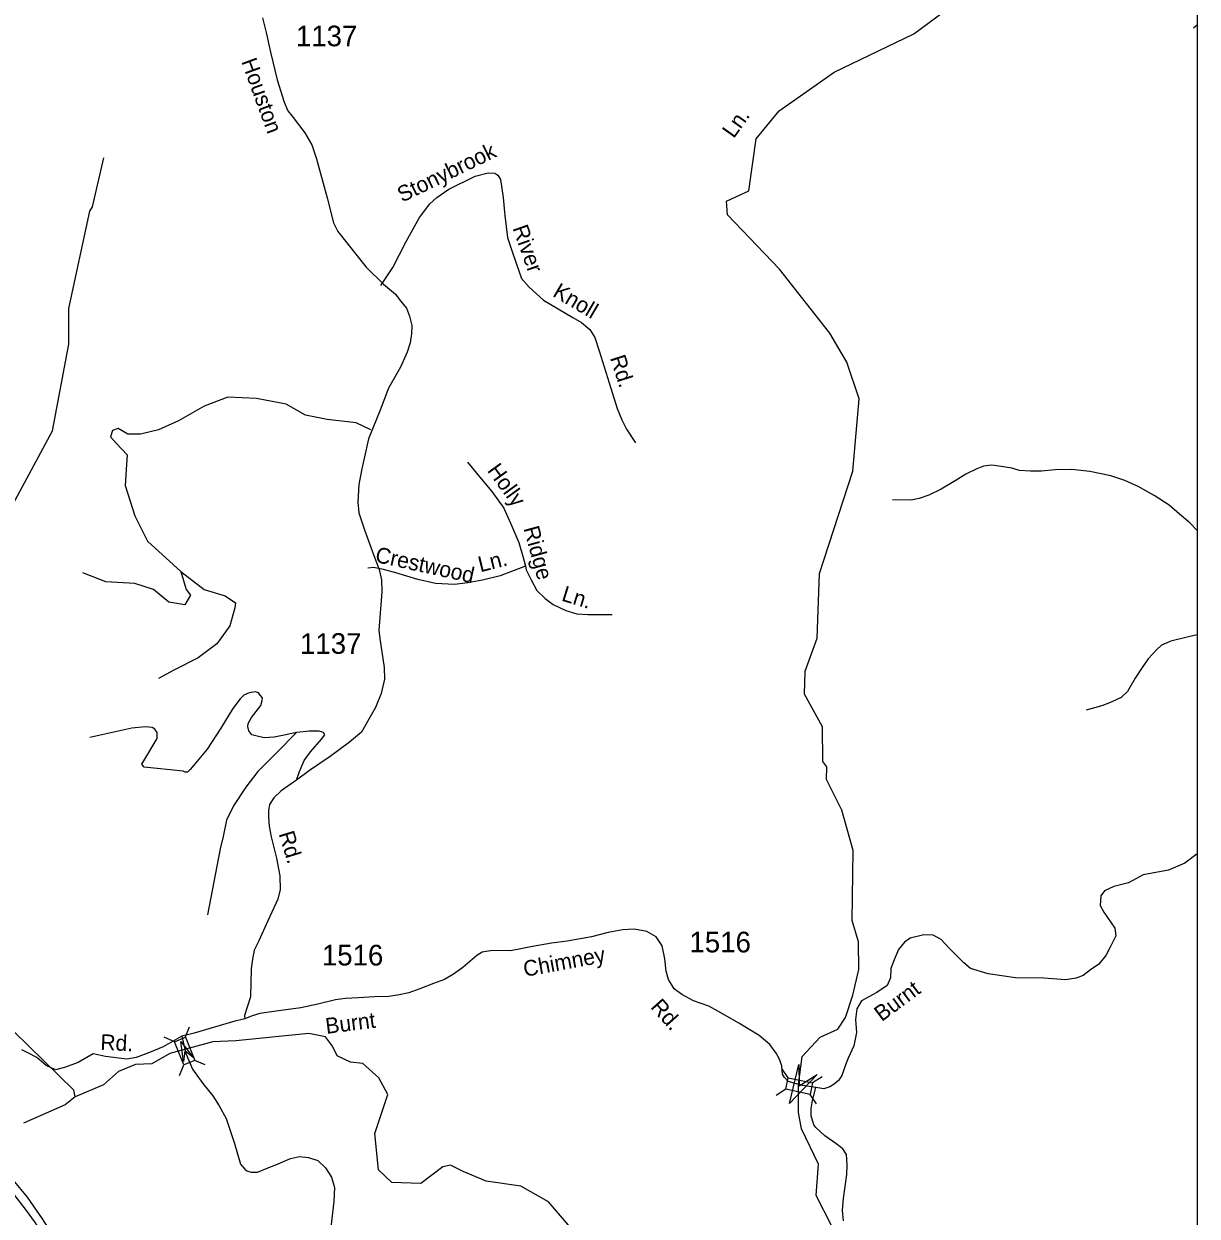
# Model space of a CAD drawing. Extents: x 990631 to 1056237, y 535999 to 585651.
# Drawn here: x 1049136 to 1056237, y 547778 to 554992 of the extents above; entities that cross this region are included whole.
import ezdxf

# ---------------------------------------------------------------- set-up
doc = ezdxf.new("R2010")
doc.units = 0
for name, color, linetype in [('Exist Hydrographic Creek Single Shore', 7, 'Continuous'), ('Exist Hydrographic River Shore', 7, 'Continuous'), ('Exist Road Non-System Type 51', 7, 'Continuous'), ('Exist Road Non-System Type 51 Label', 7, 'Continuous'), ('Exist Road Primary Interstate Divided Center Attributed', 7, 'Continuous'), ('Exist Road Secondary Structure Standard Bridge Attributed CELL', 7, 'Continuous'), ('Exist Road Secondary Structure Standard Bridge CELL', 7, 'Continuous'), ('Exist Road Secondary Type 41 Attributed', 7, 'Continuous'), ('Exist Road Secondary Type 51 Attributed', 7, 'Continuous'), ('Exist Road Secondary Type 51 Label', 7, 'Continuous'), ('Exist Road Secondary Type 51 Number Label', 7, 'Continuous'), ('Scratch_Level_3', 7, 'Continuous')]:
    doc.layers.add(name, color=color, linetype=linetype)

msp = doc.modelspace()

# ---------------------------------------------------------------- linework, layer by layer
at = {"layer": 'Exist Hydrographic Creek Single Shore'}
for points in [[(1054026.1, 547717), (1053932.1, 547902.7), (1053946.4, 548092.7), (1053842.6, 548306.8), (1053823.7, 548405.3), (1053823.7, 548573.1), (1053846.1, 548744.2), (1053956.3, 548860.9), (1054061.6, 548909.5), (1054109.6, 548980.8), (1054152.6, 549114.5), (1054190.6, 549271.3), (1054187.5, 549438.7), (1054149.6, 549567.5), (1054155.5, 549990.7), (1054087.6, 550234.9), (1053993.5, 550420.6), (1053996.5, 550496), (1053972.5, 550529.4), (1053970.6, 550739.4), (1053860.6, 550935.3), (1053864.6, 551076.3), (1053937.6, 551275), (1053950.6, 551665.4), (1054153.5, 552284.9), (1054192.5, 552723.9), (1054116.6, 552945.3), (1054013.5, 553121.3), (1053709.5, 553508.2), (1053394.5, 553836.1), (1053388.5, 553918.3), (1053524.5, 553981.2), (1053567.5, 554295.4), (1053706.5, 554466.5), (1054039.5, 554699.4), (1054522.5, 554932.6), (1055342.5, 555539.7)], [(1049445.6, 548500.3), (1049438.6, 548539.9), (1049074.6, 548895.1), (1048962.6, 549041.8), (1048753.5, 549531.7), (1048626.9, 549744.3), (1048588.6, 549843.6), (1048613.7, 550368.2), (1048706.6, 550648.6), (1048756.5, 550923.2), (1048869.5, 551337.8), (1048953.6, 551874.3), (1049308.5, 552530.1), (1049408.5, 553053.3), (1049407.6, 553269.9), (1049534.5, 553858.1), (1049551.5, 553884), (1049619.5, 554181.3)]]:
    msp.add_lwpolyline(points, dxfattribs=at)
at = {"layer": 'Exist Hydrographic River Shore'}
for points in [[(1052433.3, 547724), (1052310.6, 547865), (1052143.3, 547959.4), (1051933.2, 547988.8), (1051794.6, 548047.7), (1051719, 548085.5), (1051672.7, 548077.1), (1051538.3, 547976.2), (1051362.8, 547980.9), (1051281.8, 548058), (1051261, 548278.9), (1051339.6, 548514.8), (1051284.6, 548614.3), (1051186.6, 548701.6), (1051112.7, 548710.5), (1051032.9, 548748.4), (1051003.5, 548807.2), (1050961.5, 548861.9), (1050860.6, 548882.9), (1050419.4, 548838.5), (1050280.3, 548832.3), (1050018.5, 548762.1), (1049910.4, 548700.3), (1049812.6, 548695.1), (1049709.7, 548653.9), (1049617.1, 548571.5), (1049445.6, 548500.3)], [(1049445.6, 548500.3), (1049386.5, 548452.3), (1049133.3, 548339.8)]]:
    msp.add_lwpolyline(points, dxfattribs=at)
at = {"layer": 'Exist Road Non-System Type 51'}
for points in [[(1056237.4, 554985.1), (1056214.6, 554966.8)], [(1051297.3, 553409.4), (1051368.9, 553517.2), (1051449.9, 553674.7), (1051530.7, 553820.3), (1051593.4, 553902.3), (1051634.6, 553940.8), (1051708.2, 553992.6), (1051866.8, 554069.6), (1051945.7, 554091), (1051985.6, 554087.8), (1052005.2, 554077.2), (1052020.3, 554050.7), (1052036.9, 553941.9), (1052045.9, 553851.7)], [(1052045.9, 553851.7), (1052047.3, 553831.7), (1052063.2, 553699.1), (1052088.7, 553620.2), (1052118, 553537.2), (1052147.3, 553452.1), (1052193.6, 553398.6), (1052281.1, 553319.8), (1052457.8, 553216), (1052511, 553184.3), (1052561.6, 553142.7), (1052592, 553093.7), (1052617.4, 553012.7), (1052679.4, 552820.6), (1052726.4, 552665), (1052754.3, 552596.2), (1052784.3, 552539.2), (1052837.9, 552457.3)], [(1051236.4, 552535.5), (1051148.2, 552577.6), (1050971.7, 552598.6), (1050841.5, 552623.8), (1050723.8, 552691.1), (1050543.1, 552724.7), (1050370.9, 552733.1), (1050228, 552678.5), (1050072.5, 552590.2), (1049950.7, 552535.5), (1049841.4, 552510.3), (1049765.8, 552510.3), (1049707, 552543.9), (1049673.4, 552531.3), (1049660.8, 552493.5), (1049694.4, 552455.7), (1049761.6, 552384.2), (1049757.4, 552325.4), (1049749, 552199.2), (1049807.8, 552014.3), (1049883.4, 551863), (1050085.1, 551678), (1050228, 551568.7), (1050354, 551530.9), (1050417.1, 551488.9), (1050412.9, 551459.4), (1050383.5, 551350.1), (1050303.6, 551240.8), (1050190.2, 551156.8), (1050043.1, 551081.1), (1049950.7, 551030.7)], [(1051821.4, 552339.9), (1051896.6, 552249.3), (1051967.9, 552163.1), (1052040.7, 552062.6), (1052089.1, 551953), (1052132.1, 551853.7), (1052157.1, 551762.7), (1052171.4, 551710.2)], [(1056237.4, 551926.9), (1056192.5, 551973.6), (1056130.1, 552025.4), (1056067.8, 552079.5), (1055977.7, 552138.5), (1055879.4, 552193.7), (1055800.5, 552228.1), (1055715.2, 552257.1), (1055587.9, 552283), (1055478.3, 552294.7), (1055378.3, 552293.9), (1055295.9, 552286.5), (1055227.8, 552284.7), (1055161.9, 552288.8), (1055116.4, 552304.1), (1055038.8, 552316.7), (1054992.9, 552322.2), (1054944.6, 552315.8), (1054904, 552299), (1054836.9, 552267.2), (1054773.7, 552227.2), (1054688.1, 552175.9), (1054612.9, 552140.2), (1054554.1, 552120.2), (1054505.9, 552109.8), (1054393.6, 552111.2)], [(1050085.1, 551678), (1050118.7, 551568.7), (1050144, 551535.1), (1050110.3, 551476.2), (1050013.7, 551493.1), (1049921.3, 551568.7), (1049807.8, 551606.5), (1049631.3, 551615), (1049492.7, 551669.6)], [(1052171.4, 551710.2), (1052019.4, 551653.1), (1051912.6, 551626.4), (1051823.9, 551609.4), (1051741.6, 551599.8), (1051627.7, 551605.5), (1051520.4, 551629.1), (1051387.5, 551669.4), (1051312.1, 551689.7), (1051252.5, 551701.7), (1051218.5, 551698.8)], [(1052171.4, 551710.2), (1052176.8, 551688.1), (1052206.7, 551627.1), (1052240.9, 551564), (1052291.3, 551514.3), (1052340.2, 551478.5), (1052416.9, 551442.2), (1052482.3, 551422.1), (1052550.3, 551417.9), (1052696.5, 551419.1)], [(1056237.4, 551295.5), (1056184.4, 551283.3), (1056077.4, 551256.6), (1056020.7, 551232.5), (1055993.8, 551207.3), (1055940, 551149.1), (1055904.2, 551098.2), (1055862.2, 551033.5), (1055815.6, 550953), (1055778.2, 550916.1), (1055721.5, 550889.8), (1055666.6, 550867.5), (1055565.6, 550838.8)], [(1050786.3, 550703.9), (1050711.7, 550688.2), (1050651.3, 550676.2), (1050591.2, 550672.1), (1050547.3, 550681.5), (1050515.7, 550690.6), (1050498.4, 550715.1), (1050491.3, 550741.5), (1050493.9, 550759.2), (1050513, 550794.7), (1050569.3, 550867), (1050578.3, 550898.8), (1050580.8, 550914.7), (1050565.4, 550931.1), (1050555.8, 550943.5), (1050537.9, 550950), (1050499.8, 550945.2), (1050467.3, 550930.2), (1050444.4, 550907.1), (1050400.7, 550850.4), (1050328.8, 550730.6), (1050244.7, 550603.2), (1050165.5, 550505.8), (1050142.7, 550480.4), (1050126.2, 550464.9), (1050112, 550463.4), (1050100.3, 550469.7), (1049864.9, 550495.4), (1049849.5, 550513.7), (1049874.7, 550553), (1049919.2, 550627.6), (1049942.7, 550668.9), (1049941.8, 550704.9), (1049928.4, 550725.4), (1049912.6, 550733.9), (1049872.9, 550739.1), (1049790.4, 550729.8), (1049534.4, 550674.1)], [(1050786.3, 550703.9), (1050668.4, 550585.7), (1050552.4, 550467.4), (1050479.5, 550373.6), (1050403.8, 550259.9), (1050363, 550173.1), (1050341.9, 550075.7), (1050323.3, 550000.2), (1050248.4, 549600.4)], [(1050787.1, 550415.6), (1050804.7, 550469.3), (1050832.9, 550534.3), (1050870.5, 550587.2), (1050937.1, 550663.1), (1050957.9, 550690.5), (1050950.3, 550704.6), (1050922.7, 550711.6), (1050862.6, 550711.4), (1050788.3, 550703.9), (1050786.3, 550703.9)]]:
    msp.add_lwpolyline(points, dxfattribs=at)
at = {"layer": 'Exist Road Primary Interstate Divided Center Attributed'}
for points in [[(1048648.3, 548343.5), (1048842.1, 548163), (1048954.9, 548052.9), (1049062, 547926.9), (1049143.7, 547821.1), (1049204, 547738), (1049284.4, 547609.3), (1049356.7, 547472.6), (1049425, 547329.3), (1049509.4, 547124.2), (1049549.6, 547007.6), (1049581.7, 546891.1), (1049621.9, 546762.4), (1049656.8, 546560.1), (1049680.9, 546403.3), (1049711.7, 546213), (1049746.5, 546005.3), (1049757.2, 545922.2)], [(1049819, 545894.4), (1049802.8, 546008), (1049773.3, 546174.1), (1049742.5, 546384.5), (1049721, 546522.5), (1049683.5, 546757), (1049644.7, 546887), (1049593.8, 547058.6), (1049541.6, 547196.6), (1049477.3, 547350.7), (1049390.2, 547528.9), (1049331.3, 547632.1), (1049249.5, 547760.8), (1049157.1, 547893.4), (1049071.4, 547997.9), (1048972.3, 548110.5), (1048723.8, 548356.2)]]:
    msp.add_lwpolyline(points, dxfattribs=at)
at = {"layer": 'Exist Road Secondary Structure Standard Bridge Attributed CELL'}
for points in [[(1050102.7, 548713.1), (1050086, 548833.9), (1050160.8, 548737.7), (1050109.7, 548777.8)], [(1053937.5, 548635.5), (1053769.3, 548458.9), (1053826.7, 548695.9), (1053827.7, 548566)]]:
    msp.add_lwpolyline(points, close=True, dxfattribs=at)
at = {"layer": 'Exist Road Secondary Structure Standard Bridge CELL'}
for p, q in [((1050112.5, 548859.5), (1050139.4, 548923)), ((1050048.5, 548833.6), (1049985, 548860.6)), ((1050233.8, 548692.9), (1050170.3, 548719.8)), ((1050077.9, 548629.9), (1050104.8, 548693.4)), ((1053761.5, 548614), (1053724, 548671.9)), ((1053967.5, 548621.4), (1053909.6, 548583.8)), ((1053747.2, 548546.5), (1053689.3, 548508.9)), ((1053932.5, 548456.9), (1053894.9, 548514.8))]:
    msp.add_line(p, q, dxfattribs=at)
for points in [[(1050104.8, 548693.4), (1050048.2, 548833.5), (1050113.7, 548859.9), (1050170.3, 548719.8)], [(1053894.9, 548514.8), (1053747.1, 548546.2), (1053761.8, 548615.2), (1053909.6, 548583.8)]]:
    msp.add_lwpolyline(points, close=True, dxfattribs=at)
at = {"layer": 'Exist Road Secondary Type 41 Attributed'}
for points in [[(1056237.4, 549970.7), (1056163.4, 549913.3), (1056063.8, 549871.1), (1055910.5, 549843), (1055822.3, 549795.7), (1055732.9, 549772.6), (1055676.7, 549747.1), (1055655, 549715.1), (1055649.8, 549657.2), (1055671.6, 549618), (1055739.3, 549520.8), (1055744.3, 549473.5), (1055711, 549404.9), (1055683.9, 549354.9), (1055642.3, 549302.9), (1055592.3, 549267.5), (1055546.5, 549234.2), (1055504.9, 549217.5), (1055440.4, 549207.1), (1055309.2, 549217.5), (1055137.5, 549220.6), (1054972, 549244.6), (1054865.9, 549275.8), (1054824.2, 549311.5), (1054738.9, 549398.3), (1054688.6, 549451.9), (1054639.5, 549477.5), (1054583.5, 549479.4), (1054501.3, 549460.7), (1054465.6, 549436.4), (1054429.8, 549390.4), (1054402.9, 549329.1), (1054383.8, 549275.4), (1054381.2, 549219.1), (1054362.1, 549173.1), (1054299.5, 549130.9), (1054206.2, 549081), (1054176.8, 549032.5), (1054169.2, 548967.3), (1054176.3, 548890), (1054160.2, 548808.8), (1054124.4, 548733.3), (1054112.9, 548703.9), (1054086.1, 548628.5), (1054065.7, 548599.1), (1054040.1, 548576.2), (1054013.6, 548561), (1053977.1, 548548.1), (1053929.5, 548555.7)], [(1053739.1, 548617.1), (1053728, 548637.5), (1053724.3, 548687.5), (1053707.7, 548732), (1053689.1, 548763.5), (1053650.3, 548817.2), (1053587.3, 548871), (1053463.2, 548945.1), (1053341, 549015.5), (1053281.7, 549048.8), (1053189.8, 549079.8), (1053118.9, 549118.2), (1053072, 549153.5), (1053037.7, 549210.7), (1053023.4, 549261.2), (1053015.9, 549335.5), (1053000.3, 549413.9), (1052963.2, 549467.6), (1052905.8, 549501), (1052829.9, 549513.9), (1052761.4, 549510.2), (1052672.5, 549493.6), (1052570.6, 549467.6), (1052424.3, 549441.7), (1052329.9, 549430.6), (1052215.1, 549410.2), (1052154, 549397.2), (1052080.7, 549383.6), (1051972.7, 549385), (1051910.3, 549375), (1051877.6, 549354.1), (1051793.4, 549282.7), (1051735.9, 549242.5), (1051680.9, 549210.2), (1051616.2, 549186.3), (1051533.1, 549152.9), (1051466.2, 549129.1), (1051407.7, 549116.8), (1051345.5, 549106.9), (1051259.2, 549105.6), (1051161.1, 549098.8), (1051082.8, 549095.4), (1051022.6, 549087.2), (1050915.6, 549060.7), (1050812.9, 549038), (1050662.1, 549018.8), (1050563.5, 549004), (1050517, 548989.3), (1050472.4, 548970.8)], [(1050472.4, 548970.8), (1050448.2, 548966.5), (1050412.2, 548956.7), (1050167.4, 548884.9), (1050092.4, 548866.6)], [(1050092.4, 548866.6), (1049978.6, 548802.9), (1049896.7, 548768.7), (1049816.5, 548737.7), (1049760.1, 548727.5), (1049630.4, 548743.7), (1049555.3, 548759.6), (1049465.4, 548707), (1049382.4, 548677.5), (1049327.9, 548663.4), (1049270.9, 548689), (1049214, 548736.9), (1049163.9, 548764.2), (1049123, 548784.7)], [(1053929.5, 548555.7), (1053847.9, 548568.3), (1053762.6, 548593), (1053739.1, 548617.1)], [(1054097.7, 547749.8), (1054091.8, 547813.9), (1054096, 547883.9), (1054116.7, 548029.3), (1054118.5, 548089.3), (1054115.5, 548151.7), (1054092.5, 548184.9), (1054050.3, 548216.9), (1053983.9, 548262.9), (1053929, 548314), (1053918.1, 548330), (1053902, 548384.6), (1053901.3, 548428.6), (1053908.9, 548478.3), (1053929.5, 548555.7)]]:
    msp.add_lwpolyline(points, dxfattribs=at)
at = {"layer": 'Exist Road Secondary Type 51 Attributed'}
for points in [[(1050580.6, 555029.3), (1050601.9, 554939.4), (1050629.6, 554819.9), (1050668.9, 554653.1), (1050711.4, 554517.3), (1050734.3, 554466.6), (1050760.4, 554433.9), (1050835.7, 554332.4), (1050879.8, 554260.4), (1050907.6, 554175.4), (1050971.4, 553939.8), (1051010.6, 553787.7), (1051036.8, 553735.3), (1051208.4, 553519.4), (1051313.1, 553417.9), (1051385, 553357.4), (1051414.4, 553318.1), (1051452, 553272.3), (1051470, 553223.2), (1051484.7, 553167.6), (1051483.1, 553116.9), (1051474.9, 553062.9), (1051455.3, 553005.7), (1051416.1, 552915.7), (1051342.5, 552788.1), (1051291.8, 552655.6), (1051221.5, 552482.2), (1051180.6, 552298.9), (1051162.6, 552205.7), (1051157.7, 552097.7), (1051162.6, 552033.9), (1051198.6, 551930.8), (1051254.2, 551775.4), (1051286.9, 551690.4), (1051300, 551628.2), (1051301.6, 551556.2), (1051288.5, 551373), (1051283.6, 551323.9), (1051290.2, 551273.2), (1051316.3, 551098.1), (1051318, 551026.2), (1051298.3, 550939.4), (1051264, 550856), (1051223.1, 550786), (1051178.6, 550705.4), (1051107.1, 550645), (1050989.3, 550558.3), (1050865.1, 550474.8), (1050787.1, 550415.6), (1050781, 550411.9), (1050693.4, 550352.1), (1050649.5, 550309.9), (1050623.1, 550268.7), (1050616.6, 550232.7), (1050616.6, 550191.8), (1050621.5, 550137.8), (1050632.9, 550074), (1050665.6, 549944.8), (1050685.2, 549836.8), (1050686.9, 549755), (1050673.8, 549696.1), (1050613.3, 549565.2), (1050558.5, 549443.4), (1050529.1, 549387.7), (1050519.3, 549332.1), (1050511.9, 549277.3), (1050507, 549105.5), (1050471.9, 548992.8), (1050472.4, 548970.8)], [(1050092.4, 548866.6), (1050112.8, 548777.5)], [(1050112.8, 548777.5), (1050117.4, 548757.4), (1050156.1, 548666.3), (1050219.8, 548579.8), (1050278.9, 548506.9), (1050317.6, 548445.4), (1050360.9, 548368), (1050410.9, 548217.7), (1050447.3, 548092.5), (1050472.4, 548062.9), (1050486, 548051.5), (1050511.6, 548044.1), (1050549.7, 548044.7), (1050608.9, 548067.4), (1050661.2, 548087.9), (1050750, 548126.6), (1050804.6, 548138), (1050859.2, 548133.5), (1050916.1, 548115.3), (1050962.2, 548070.3), (1050998.6, 548013.4), (1051015.6, 547951.9), (1051011.1, 547866.5), (1050992.9, 547711.7)]]:
    msp.add_lwpolyline(points, dxfattribs=at)
at = {"layer": 'Scratch_Level_3'}
msp.add_lwpolyline([(1056237.4, 535999.3), (990630.7, 535999.3), (990630.7, 585651.1), (1056237.4, 585651.1)], close=True, dxfattribs=at)

# ---------------------------------------------------------------- texts
at = {"layer": 'Exist Road Non-System Type 51 Label'}
for s, rotation, p in [('Ln.', 54.44702, (1053432.4, 554294.3)), ('Stonybrook', 25.90602, (1051425.4, 553909.9)), ('River', 289.462, (1052092.7, 553756.6)), ('Knoll', 329.57917, (1052331, 553347.5)), ('Rd.', 287.8727, (1052682.5, 552971.3)), ('Holly', 305.91807, (1051937.1, 552289.4)), ('Ridge', 285.35849, (1052159.5, 551939.7)), ('Crestwood', 347.61769, (1051257.3, 551737.2)), ('Ln.', 14.01936, (1051898.7, 551673.6)), ('Ln.', 342.9003, (1052385.3, 551503.4))]:
    msp.add_text(s, height=95, rotation=rotation, dxfattribs=at).set_placement(p)
at = {"layer": 'Exist Road Secondary Type 51 Label'}
for s, rotation, p in [('Houston', 290.00372, (1050450.7, 554764.7)), ('Rd.', 287.00715, (1050677.4, 550091.8)), ('Chimney', 10.42356, (1052167.9, 549225.4)), ('Burnt', 36.64029, (1054327.8, 548951.8)), ('Rd.', 311.84264, (1052924.1, 549040.6)), ('Burnt', 7.24286, (1050967.3, 548880.6)), ('Rd.', 357.32773, (1049597.4, 548784.3))]:
    msp.add_text(s, height=95, rotation=rotation, dxfattribs=at).set_placement(p)
at = {"layer": 'Exist Road Secondary Type 51 Number Label'}
for s, p in [('1137', (1050782.3, 554856.5)), ('1137', (1050807.4, 551180.3)), ('1516', (1053164.5, 549373.8)), ('1516', (1050939.7, 549294.6))]:
    msp.add_text(s, height=125, dxfattribs=at).set_placement(p)

doc.saveas('drawing.dxf')
